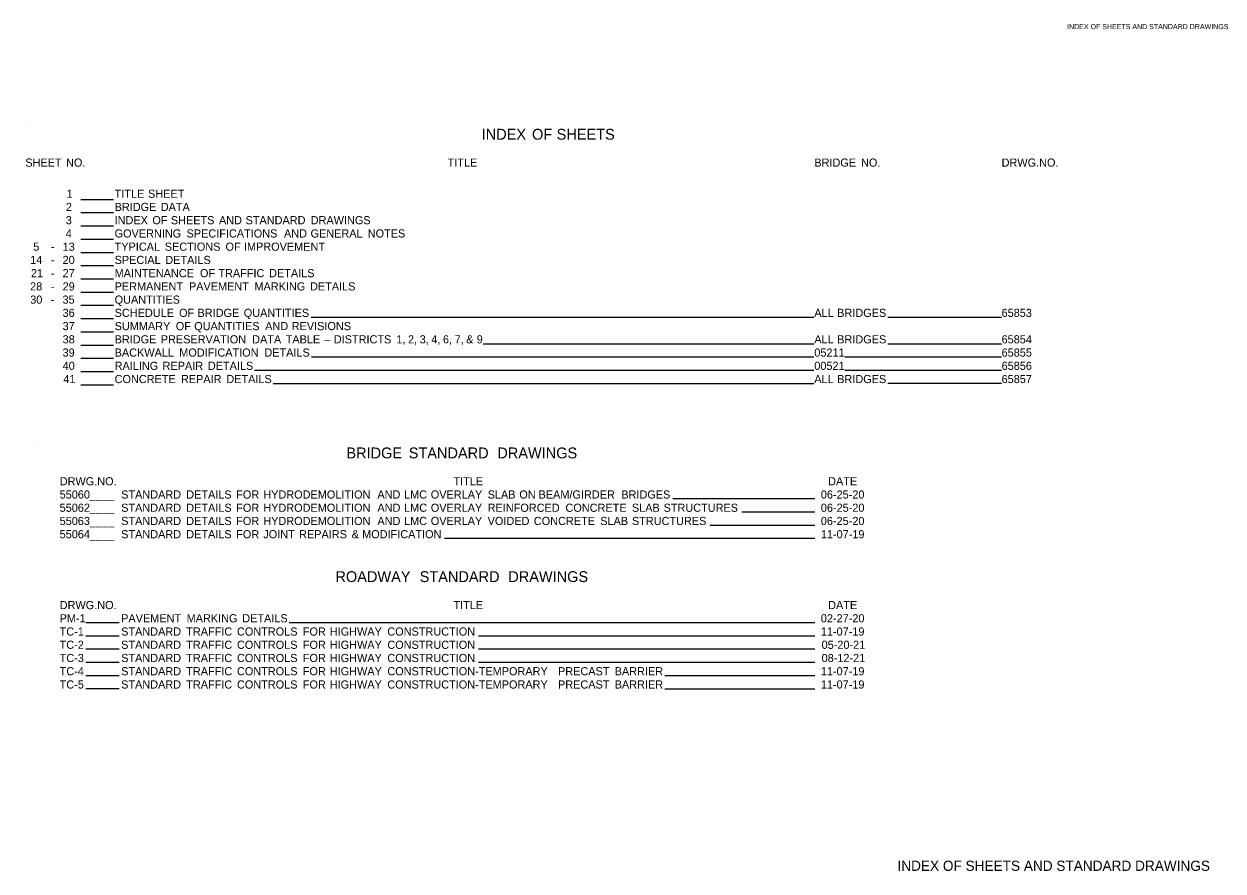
# Model space of a CAD drawing. Extents: x 3046 to 29176, y -9559 to 572.
# Drawn here: x 27763 to 29176, y -9559 to -8560 of the extents above; entities that cross this region are included whole.
import ezdxf

# ---------------------------------------------------------------- set-up
doc = ezdxf.new("R2010")
doc.units = 0
for name, color, linetype in [('Default', 7, 'Continuous'), ('R_Annotation', 7, 'Continuous'), ('R_Border', 7, 'Continuous')]:
    doc.layers.add(name, color=color, linetype=linetype)

msp = doc.modelspace()

# ---------------------------------------------------------------- linework, layer by layer
at = {"layer": 'Default'}
for p, q in [((27830.6, -8767), (27868.8, -8767)), ((27830.6, -8782.6), (27868.8, -8782.6)), ((27830.6, -8798.2), (27868.8, -8798.2)), ((27830.6, -8813.8), (27868.8, -8813.8)), ((27830.6, -8829.4), (27868.8, -8829.4)), ((27830.6, -8845), (27868.8, -8845)), ((27830.6, -8860.6), (27868.8, -8860.6)), ((27830.6, -8876.2), (27868.8, -8876.2)), ((27830.6, -8891.8), (27868.8, -8891.8)), ((27830.6, -8907.4), (27868.8, -8907.4)), ((28102, -8905.9), (28694.3, -8905.9)), ((28781.6, -8905.9), (28915.5, -8905.9)), ((27830.6, -8923), (27868.8, -8923)), ((27830.6, -8938.6), (27868.8, -8938.6)), ((28304.5, -8937.1), (28694.3, -8937.1)), ((28781.3, -8937.1), (28915.5, -8937.1)), ((27830.6, -8954.2), (27868.8, -8954.2)), ((28102.2, -8952.7), (28694.3, -8952.7)), ((28730.6, -8952.7), (28915.5, -8952.7)), ((27830.6, -8969.8), (27868.8, -8969.8)), ((28035.1, -8968.3), (28694.3, -8968.3)), ((28730.6, -8968.3), (28915.5, -8968.3)), ((27830.6, -8985.4), (27868.8, -8985.4)), ((28057.1, -8983.9), (28694.3, -8983.9)), ((28781.3, -8983.6), (28915.5, -8983.6)), ((28528.2, -9119.7), (28695.4, -9119.7)), ((28609.5, -9135.2), (28695.4, -9135.2)), ((28571.6, -9150.8), (28695.4, -9150.8)), ((28259.2, -9166.3), (28695.4, -9166.3)), ((27836.5, -9265.5), (27875.6, -9265.5)), ((28075.9, -9265.7), (28695.4, -9265.7)), ((27836.5, -9281.2), (27875.6, -9281.2)), ((28299, -9281.2), (28695.4, -9281.2)), ((27836.5, -9296.8), (27875.6, -9296.8)), ((28299, -9296.8), (28695.4, -9296.8)), ((27836.5, -9312.4), (27875.6, -9312.4)), ((28299, -9312.5), (28695.4, -9312.5)), ((27836.5, -9328.1), (27875.6, -9328.1)), ((28518.7, -9328.1), (28695.4, -9328.1)), ((27836.5, -9343.6), (27875.6, -9343.6)), ((28518.7, -9343.8), (28695.4, -9343.8))]:
    msp.add_line(p, q, dxfattribs=at)
at = {"layer": 'R_Annotation'}
for p, q in [((27763.5, -8678.1), (27763.5, -8678.1)), ((27775.1, -9053.7), (27775.1, -9053.7))]:
    msp.add_line(p, q, dxfattribs=at)

# ---------------------------------------------------------------- texts
at = {"layer": 'Default'}
for s, height, p in [('INDEX', 12.8, (28302.8, -8696.6)), (' OF', 12.8, (28357.4, -8696.6)), (' SHEETS', 12.8, (28386.4, -8696.6)), ('SHEET', 9.6, (27765, -8728.4)), (' NO.', 9.6, (27809.5, -8728.4)), ('TITLE', 9.6, (28262.7, -8728.4)), ('BRIDGE', 9.6, (28694.8, -8728.4)), (' NO.', 9.6, (28746.3, -8728.4)), ('DRWG.NO.', 9.6, (28915.5, -8728.4)), ('1', 9.6, (27813.6, -8765.1)), ('TITLE', 9.6, (27870.3, -8765.1)), (' SHEET', 9.6, (27906.1, -8765.1)), ('2', 9.6, (27812.8, -8780.7)), ('BRIDGE', 9.6, (27870.3, -8780.7)), (' DATA', 9.6, (27921.1, -8780.7)), ('3', 9.6, (27812.7, -8796.3)), ('INDEX', 9.6, (27870.3, -8796.3)), (' OF', 9.6, (27911.2, -8796.3)), (' SHEETS', 9.6, (27933, -8796.3)), (' AND', 9.6, (27989.7, -8796.3)), (' STANDARD', 9.6, (28021, -8796.3)), (' DRAWINGS', 9.6, (28097.8, -8796.3)), ('4', 9.6, (27812.7, -8811.9)), ('GOVERNING', 9.6, (27870.3, -8811.9)), (' SPECIFICATIONS', 9.6, (27951.5, -8811.9)), (' AND', 9.6, (28066.3, -8811.9)), (' GENERAL', 9.6, (28097.6, -8811.9)), (' NOTES', 9.6, (28165, -8811.9)), ('5', 9.6, (27774.4, -8827.5)), ('-', 9.6, (27795, -8827.5)), ('13', 9.6, (27809, -8827.5)), ('TYPICAL', 9.6, (27870.3, -8827.5)), (' SECTIONS', 9.6, (27925.8, -8827.5)), (' OF', 9.6, (27997.4, -8827.5)), (' IMPROVEMENT', 9.6, (28019.1, -8827.5)), ('14', 9.6, (27770.8, -8843.1)), ('-', 9.6, (27795, -8843.1)), ('20', 9.6, (27809, -8843.1)), ('SPECIAL', 9.6, (27870.3, -8843.1)), (' DETAILS', 9.6, (27926.5, -8843.1)), ('21', 9.6, (27771.7, -8858.7)), ('-', 9.6, (27795, -8858.7)), ('27', 9.6, (27809, -8858.7)), ('MAINTENANCE', 9.6, (27870.3, -8858.7)), (' OF', 9.6, (27967.3, -8858.7)), (' TRAFFIC', 9.6, (27989, -8858.7)), (' DETAILS', 9.6, (28048.8, -8858.7)), ('28', 9.6, (27770.7, -8874.3)), ('-', 9.6, (27795, -8874.3)), ('29', 9.6, (27809, -8874.3)), ('PERMANENT', 9.6, (27870.3, -8874.3)), (' PAVEMENT', 9.6, (27954.3, -8874.3)), (' MARKING', 9.6, (28031.5, -8874.3)), (' DETAILS', 9.6, (28097, -8874.3)), ('30', 9.6, (27770.8, -8889.9)), ('-', 9.6, (27795, -8889.9)), ('35', 9.6, (27808.9, -8889.9)), ('QUANTITIES', 9.6, (27870.3, -8889.9)), ('36', 9.6, (27809, -8905.5)), ('SCHEDULE', 9.6, (27870.3, -8905.5)), (' OF', 9.6, (27942.7, -8905.5)), (' BRIDGE', 9.6, (27964.4, -8905.5)), (' QUANTITIES', 9.6, (28018.9, -8905.5)), ('ALL', 9.6, (28694.8, -8905.5)), (' BRIDGES', 9.6, (28718.2, -8905.5)), ('65853', 9.6, (28915.5, -8905.5)), ('37', 9.6, (27809, -8921.1)), ('SUMMARY', 9.6, (27870.3, -8921.1)), (' OF', 9.6, (27938.8, -8921.1)), (' QUANTITIES', 9.6, (27960.5, -8921.1)), (' AND', 9.6, (28044.1, -8921.1)), (' REVISIONS', 9.6, (28075.4, -8921.1)), ('38', 9.6, (27809, -8936.7)), ('BRIDGE', 9.6, (27870.3, -8936.7)), (' PRESERVATION', 9.6, (27921.1, -8936.7)), (' DATA', 9.6, (28028.8, -8936.7)), (' TABLE', 9.6, (28068.3, -8936.7)), (' DISTRICTS', 9.6, (28125, -8936.7)), (' 1,', 9.6, (28198.8, -8936.7)), (' 2,', 9.6, (28212.5, -8936.7)), (' 3,', 9.6, (28226.2, -8936.7)), (' 4,', 9.6, (28239.9, -8936.7)), (' 6,', 9.6, (28253.6, -8936.7)), (' 7,', 9.6, (28267.4, -8936.7)), (' &', 9.6, (28281.1, -8936.7)), (' 9', 9.6, (28293.4, -8936.7)), ('ALL', 9.6, (28694.8, -8936.7)), (' BRIDGES', 9.6, (28718.2, -8936.7)), ('65854', 9.6, (28915.5, -8936.7)), ('39', 9.6, (27809, -8952.3)), ('BACKWALL', 9.6, (27870.3, -8952.3)), (' MODIFICATION', 9.6, (27942.9, -8952.3)), (' DETAILS', 9.6, (28043.2, -8952.3)), ('–', 9.6, (28117.5, -8936.7)), ('05211', 9.6, (28694.8, -8952.3)), ('65855', 9.6, (28915.5, -8952.3)), ('40', 9.6, (27809, -8967.9)), ('RAILING', 9.6, (27870.3, -8967.9)), (' REPAIR', 9.6, (27923.2, -8967.9)), (' DETAILS', 9.6, (27976.6, -8967.9)), ('00521', 9.6, (28694.8, -8967.9)), ('65856', 9.6, (28915.5, -8967.9)), ('41', 9.6, (27809.9, -8983.5)), ('CONCRETE', 9.6, (27870.3, -8983.5)), (' REPAIR', 9.6, (27944.9, -8983.5)), (' DETAILS', 9.6, (27998.4, -8983.5)), ('ALL', 9.6, (28694.8, -8983.5)), (' BRIDGES', 9.6, (28718.2, -8983.5)), ('65857', 9.6, (28915.5, -8983.5))]:
    msp.add_text(s, height=height, dxfattribs=at).set_placement(p)
for s, height, p in [('BRIDGE', 12.8, (28143.4, -9072.2)), (' STANDARD', 12.8, (28212.1, -9072.2)), (' DRAWINGS', 12.8, (28316.5, -9072.2)), ('DRWG.NO.', 9.6, (27805.6, -9104)), ('TITLE', 9.6, (28269.6, -9104)), ('DATE', 9.6, (28711.1, -9104)), ('55060____', 9.6, (27805.5, -9119.6)), ('STANDARD', 9.6, (27878, -9119.6)), (' DETAILS', 9.6, (27951.1, -9119.6)), (' FOR', 9.6, (28010, -9119.6)), (' HYDRODEMOLITION', 9.6, (28041.9, -9119.6)), (' AND', 9.6, (28176.4, -9119.6)), (' LMC', 9.6, (28207.8, -9119.6)), (' OVERLAY', 9.6, (28239.3, -9119.6)), (' SLAB', 9.6, (28306.3, -9119.6)), (' ON', 9.6, (28343.6, -9119.6)), (' BEAM/GIRDER', 9.6, (28366.3, -9119.6)), (' BRIDGES', 9.6, (28463.8, -9119.6)), ('06-25-20', 9.6, (28702.5, -9119.6)), ('55062____', 9.6, (27805.5, -9135.2)), ('STANDARD', 9.6, (27878, -9135.2)), (' DETAILS', 9.6, (27951.1, -9135.2)), (' FOR', 9.6, (28010, -9135.2)), (' HYDRODEMOLITION', 9.6, (28041.9, -9135.2)), (' AND', 9.6, (28176.4, -9135.2)), (' LMC', 9.6, (28207.8, -9135.2)), (' OVERLAY', 9.6, (28239.3, -9135.2)), (' REINFORCED', 9.6, (28306.3, -9135.2)), (' CONCRETE', 9.6, (28398, -9135.2)), (' SLAB', 9.6, (28476.3, -9135.2)), (' STRUCTURES', 9.6, (28513.6, -9135.2)), ('06-25-20', 9.6, (28702.5, -9135.2)), ('55063____', 9.6, (27805.5, -9150.8)), ('STANDARD', 9.6, (27878, -9150.8)), (' DETAILS', 9.6, (27951.1, -9150.8)), (' FOR', 9.6, (28010, -9150.8)), (' HYDRODEMOLITION', 9.6, (28041.9, -9150.8)), (' AND', 9.6, (28176.4, -9150.8)), (' LMC', 9.6, (28207.8, -9150.8)), (' OVERLAY', 9.6, (28239.3, -9150.8)), (' VOIDED', 9.6, (28306.3, -9150.8)), (' CONCRETE', 9.6, (28360.7, -9150.8)), (' SLAB', 9.6, (28439, -9150.8)), (' STRUCTURES', 9.6, (28476.3, -9150.8)), ('06-25-20', 9.6, (28702.5, -9150.8)), ('55064____', 9.6, (27805.5, -9166.4)), ('STANDARD', 9.6, (27878, -9166.4)), (' DETAILS', 9.6, (27951.1, -9166.4)), (' FOR', 9.6, (28010, -9166.4)), (' JOINT', 9.6, (28041.9, -9166.4)), (' REPAIRS', 9.6, (28084.1, -9166.4)), (' &', 9.6, (28146, -9166.4)), (' MODIFICATION', 9.6, (28158.4, -9166.4)), ('11-07-19', 9.6, (28702.5, -9166.4)), ('ROADWAY', 12.8, (28130.5, -9218)), (' STANDARD', 12.8, (28225, -9218)), (' DRAWINGS', 12.8, (28329.4, -9218)), ('DRWG.NO.', 9.6, (27805.6, -9249.9)), ('TITLE', 9.6, (28269.6, -9249.9)), ('DATE', 9.6, (28711.1, -9249.9)), ('PM-1', 9.6, (27805.5, -9265.5)), ('PAVEMENT', 9.6, (27878, -9265.5)), (' MARKING', 9.6, (27951.6, -9265.5)), (' DETAILS', 9.6, (28017.1, -9265.5)), ('02-27-20', 9.6, (28702.5, -9265.5)), ('TC-1', 9.6, (27805.5, -9281.1)), ('STANDARD', 9.6, (27878, -9281.1)), (' TRAFFIC', 9.6, (27951.1, -9281.1)), (' CONTROLS', 9.6, (28010.9, -9281.1)), (' FOR', 9.6, (28088.5, -9281.1)), (' HIGHWAY', 9.6, (28120.3, -9281.1)), (' CONSTRUCTION', 9.6, (28188.1, -9281.1)), ('11-07-19', 9.6, (28702.5, -9281.1)), ('TC-2', 9.6, (27805.5, -9296.7)), ('STANDARD', 9.6, (27878, -9296.7)), (' TRAFFIC', 9.6, (27951.1, -9296.7)), (' CONTROLS', 9.6, (28010.9, -9296.7)), (' FOR', 9.6, (28088.5, -9296.7)), (' HIGHWAY', 9.6, (28120.3, -9296.7)), (' CONSTRUCTION', 9.6, (28188.1, -9296.7)), ('05-20-21', 9.6, (28703.4, -9296.7)), ('TC-3', 9.6, (27805.5, -9312.3)), ('STANDARD', 9.6, (27878, -9312.3)), (' TRAFFIC', 9.6, (27951.1, -9312.3)), (' CONTROLS', 9.6, (28010.9, -9312.3)), (' FOR', 9.6, (28088.5, -9312.3)), (' HIGHWAY', 9.6, (28120.3, -9312.3)), (' CONSTRUCTION', 9.6, (28188.1, -9312.3)), ('08-12-21', 9.6, (28703.4, -9312.3)), ('TC-4', 9.6, (27805.5, -9327.9)), ('STANDARD', 9.6, (27878, -9327.9)), (' TRAFFIC', 9.6, (27951.1, -9327.9)), (' CONTROLS', 9.6, (28010.9, -9327.9)), (' FOR', 9.6, (28088.5, -9327.9)), (' HIGHWAY', 9.6, (28120.3, -9327.9)), (' CONSTRUCTION-TEMPORARY', 9.6, (28188.1, -9327.9)), (' PRECAST', 9.6, (28389.2, -9327.9)), (' BARRIER', 9.6, (28456, -9327.9)), ('11-07-19', 9.6, (28702.5, -9327.9)), ('TC-5', 9.6, (27805.5, -9343.5)), ('STANDARD', 9.6, (27878, -9343.5)), (' TRAFFIC', 9.6, (27951.1, -9343.5)), (' CONTROLS', 9.6, (28010.9, -9343.5)), (' FOR', 9.6, (28088.5, -9343.5)), (' HIGHWAY', 9.6, (28120.3, -9343.5)), (' CONSTRUCTION-TEMPORARY', 9.6, (28188.1, -9343.5)), (' PRECAST', 9.6, (28389.2, -9343.5)), (' BARRIER', 9.6, (28456, -9343.5)), ('11-07-19', 9.6, (28702.5, -9343.5))]:
    msp.add_text(s, height=height, rotation=360, dxfattribs=at).set_placement(p)
at = {"layer": 'R_Annotation'}
msp.add_text('INDEX OF SHEETS AND STANDARD DRAWINGS', height=12, rotation=360, dxfattribs=at).set_placement((28792.8, -9558.4))
at = {"layer": 'R_Border'}
msp.add_text('INDEX OF SHEETS AND STANDARD DRAWINGS', height=6, rotation=360, dxfattribs=at).set_placement((28992.7, -8566.3))

doc.saveas('drawing.dxf')
